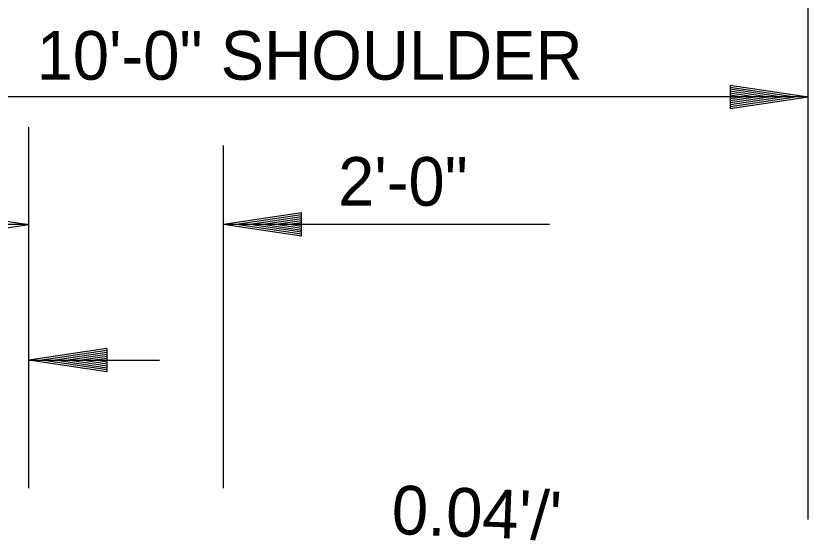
# Model space of a CAD drawing. Extents: x 60325 to 61047, y 53669 to 53767.
# Drawn here: x 60608.41 to 60616.55, y 53735.16 to 53740.42 of the extents above; entities that cross this region are included whole.
import ezdxf

# ---------------------------------------------------------------- set-up
doc = ezdxf.new("R2010")
doc.units = 0
doc.layers.add('R_Border', color=7, linetype='Continuous')
doc.layers.add('R_Border Prem', color=7, linetype='Continuous')

msp = doc.modelspace()

# ---------------------------------------------------------------- linework, layer by layer
at = {"layer": 'R_Border'}
for p, q in [((60608.5451, 53735.5712), (60608.5451, 53739.2792)), ((60609.3451, 53737.0054), (60608.5451, 53736.8854)), ((60609.3451, 53736.9854), (60608.6787, 53736.8854)), ((60609.3451, 53736.965), (60608.8163, 53736.8854)), ((60609.3451, 53736.945), (60608.9495, 53736.8854)), ((60609.3451, 53737.0054), (60609.3451, 53736.7654)), ((60608.5451, 53736.8854), (60609.8875, 53736.8854)), ((60609.3451, 53736.7654), (60608.5451, 53736.8854)), ((60609.3451, 53736.7854), (60608.6787, 53736.8854)), ((60609.3451, 53736.8058), (60608.8163, 53736.8854)), ((60609.3451, 53736.8258), (60608.9495, 53736.8854)), ((60609.3451, 53736.9242), (60609.0851, 53736.8854)), ((60609.3451, 53736.8462), (60609.0851, 53736.8854)), ((60609.3451, 53736.9042), (60609.2187, 53736.8854)), ((60609.3451, 53736.8666), (60609.2187, 53736.8854))]:
    msp.add_line(p, q, dxfattribs=at)
at = {"layer": 'R_Border Prem'}
for p, q in [((60616.5451, 53735.2512), (60616.5451, 53740.8412)), ((60615.7451, 53739.7112), (60616.5451, 53739.5912)), ((60615.7451, 53739.7112), (60615.7451, 53739.4712)), ((60615.7451, 53739.6912), (60616.4115, 53739.5912)), ((60615.7451, 53739.6708), (60616.2739, 53739.5912)), ((60615.7451, 53739.6508), (60616.1407, 53739.5912)), ((60615.7451, 53739.63), (60616.0051, 53739.5912)), ((60616.5451, 53739.5912), (60606.5451, 53739.5912)), ((60615.7451, 53739.61), (60615.8715, 53739.5912)), ((60615.7451, 53739.4712), (60616.5451, 53739.5912)), ((60615.7451, 53739.552), (60616.0051, 53739.5912)), ((60615.7451, 53739.5116), (60616.2739, 53739.5912)), ((60615.7451, 53739.4912), (60616.4115, 53739.5912)), ((60615.7451, 53739.5316), (60616.1407, 53739.5912)), ((60615.7451, 53739.5724), (60615.8715, 53739.5912)), ((60610.5451, 53735.5712), (60610.5451, 53739.0912)), ((60607.7451, 53738.3987), (60608.5451, 53738.2787)), ((60611.3451, 53738.3987), (60610.5451, 53738.2787)), ((60611.3451, 53738.3787), (60610.6787, 53738.2787)), ((60611.3451, 53738.3583), (60610.8163, 53738.2787)), ((60611.3451, 53738.3383), (60610.9495, 53738.2787)), ((60611.3451, 53738.1587), (60611.3451, 53738.3987)), ((60608.5451, 53738.2787), (60607.2028, 53738.2787)), ((60607.7451, 53738.1587), (60608.5451, 53738.2787)), ((60613.8919, 53738.2787), (60610.5451, 53738.2787)), ((60611.3451, 53738.1587), (60610.5451, 53738.2787)), ((60611.3451, 53738.1787), (60610.6787, 53738.2787)), ((60611.3451, 53738.1991), (60610.8163, 53738.2787)), ((60611.3451, 53738.2191), (60610.9495, 53738.2787)), ((60611.3451, 53738.3179), (60611.0851, 53738.2787)), ((60611.3451, 53738.2399), (60611.0851, 53738.2787)), ((60611.3451, 53738.2975), (60611.2187, 53738.2787)), ((60611.3451, 53738.2599), (60611.2187, 53738.2787))]:
    msp.add_line(p, q, dxfattribs=at)

# ---------------------------------------------------------------- texts
for s, p in [('10\'-0" SHOULDER', (60608.626, 53739.7663)), ('2\'-0"', (60611.7204, 53738.4718))]:
    msp.add_text(s, height=0.5, dxfattribs=at).set_placement(p)
msp.add_text("0.04'/'", height=0.5, rotation=357.70939, dxfattribs=at).set_placement((60612.2631, 53735.1033))

doc.saveas('drawing.dxf')
